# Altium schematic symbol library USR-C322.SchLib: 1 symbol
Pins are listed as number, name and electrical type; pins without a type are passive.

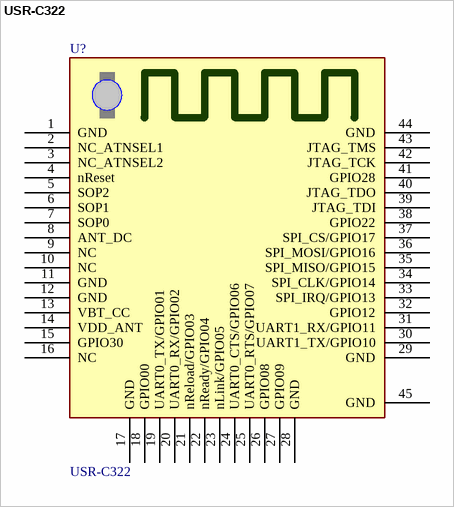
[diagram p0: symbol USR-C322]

## USR-C322
designator U?
footprint USR-WiFi232-C322
footprint USR-C322-PCB (USR-C322封装)
pins: 1 GND, 2 NC_ATNSEL1, 3 NC_ATNSEL2, 4 nReset, 5 SOP2, 6 SOP1, 7 SOP0, 8 ANT_DC, 9 NC, 10 NC, 11 GND, 12 GND, 13 VBT_CC, 14 VDD_ANT, 15 GPIO30, 16 NC, 17 GND, 18 GPIO00, 19 UART0_TX/GPIO01, 20 UART0_RX/GPIO02, 21 nReload/GPIO03, 22 nReady/GPIO04, 23 nLink/GPIO05, 24 UART0_CTS/GPIO06, 25 UART0_RTS/GPIO07, 26 GPIO08, 27 GPIO09, 28 GND, 29 GND, 30 UART1_TX/GPIO10, 31 UART1_RX/GPIO11, 32 GPIO12, 33 SPI_IRQ/GPIO13, 34 SPI_CLK/GPIO14, 35 SPI_MISO/GPIO15, 36 SPI_MOSI/GPIO16, 37 SPI_CS/GPIO17, 38 GPIO22, 39 JTAG_TDI, 40 JTAG_TDO, 41 GPIO28, 42 JTAG_TCK, 43 JTAG_TMS, 44 GND, 45 GND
